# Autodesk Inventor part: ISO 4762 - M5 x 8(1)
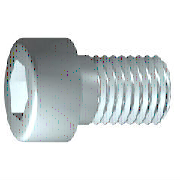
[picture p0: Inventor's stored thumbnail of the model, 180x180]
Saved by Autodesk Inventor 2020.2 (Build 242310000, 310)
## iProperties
Created: 2019-01
Part Number: ISO 4762 - M5 x 8(1)
Material: Edelstahl, 440C
Description: Innensechskantschraube
Document SubType Name: Modeling
Standard: ISO 4762
Designer: lutzd
Standard Revision: Fourth edition 2004-03-01
Standards Organization: ISO
Language: de-DE
Size Designation: M5 x 8
Categories: <MemberInstance><Categories><Category DisplayName="Verbindungselemente" InternalName="e4da775c-781d-43d5-af7c-5136215cf5a6" Mnemonic="FSTN"><Category DisplayNam
Mass: 3.06739 g
Surface Area: 3.99742 cm^2
Volume: 0.395792 cm^3
Density: 7.75 g/cm^3
Appearance: Semi-Polished(3)
IsCustomPart: 0
Author: lutzd
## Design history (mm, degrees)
body "Solid1"
sketch "Skizze1"
  geometry: L1 (-1.167, 0)-(8, 0); L2 (8, 0)-(8, 2.5); L3 (8, 2.5)-(2, 2.5); L4 (2, 2.5)-(1.509, 2.5); L5 (1.509, 2.5)-(0, 2.5); L6 (0, 2.5)-(0, 4.25); L7 (0, 4.25)-(-5, 4.25); L8 (-5, 4.25)-(-5, 2.309); L9 (-5, 2.309)-(-2.5, 2.309); L10 (-2.5, 2.309)-(-1.167, 0); L11 (-7.6, 0)-(10.6, 0) reference; L12 (0, -0.85)-(0, 5.1) reference; L13 (2, 2.5)-(0, 2.5)
  constraints: 22 end point, 6 parallel, 2 collinear, 2 perpendicular, 1 horizontal, 1 point on line
  dimensions: "d1" = 6 distance from line of L3.end L2 (= GEL); "d2" = 0.49086 distance of L4.end L3.end (computed from GAL); "d3" = 5 distance between parallel lines of L8 L6 (= KOH); "d4" = 2.5 distance of L8.end L9.end (= INTI); "d5" = 60 deg angle of L10 L1; "d6" = 5 diameter of L3 L1 (= GD); "d7" = 5 diameter of L5 L1 (= BDM); "d8" = 4.6188 diameter of L9 L1 (= 1.1547 x SW); "d9" = 8.5 diameter of L7 L1 (= KOD); "d26" = 8 distance between parallel lines of L12 L2 (= NLG)
workplane "Work Plane1"
fillet "Fillet2" dims "d30" = 0.1 (= R)
revolve "Körper" stored, may be unused: angle "d10" = 90 deg
sketch "Skizze2"
  geometry: L1 (0, -5.95)-(0, 5.95) reference; L2 (-5.95, 0)-(5.95, 0) reference; L3 (2.309, 0)-(1.155, -2); L4 (1.155, -2)-(-1.155, -2); L5 (-1.155, -2)-(-2.309, 0); L6 (-2.309, 0)-(-1.155, 2); L7 (-1.155, 2)-(1.155, 2); L8 (1.155, 2)-(2.309, 0); 2 further points
  constraints: 12 end point, 1 coincident, 1 horizontal alignment, 1 point on line, 12 other
extrude "Loch" join sketch "Skizze2" stored distance "d11" = 10; taper "d12" = 0 deg
fillet "Rundung1" dims "d17" = 0.5 (= RR)
feature "Gewinde" dims "d13" = 6 (= GEL), "d14" = 0
chamfer "Fase1" distance "d15" = 0.49076 (= -0.5 x SPD + 0.5 x GD); stored, may be unused: second distance "d16" = 0.49076 (= GUL), angle "d27" = 45 deg
other parameters: "GD" = 5 [user parameter; used in 2 equation terms], "NLG" = 8 [user parameter; used in 1 equation term], "GEL" = 6 [user parameter; used in 2 equation terms], "KOD" = 8.5 [user parameter; used in 1 equation term], "KOH" = 5 [user parameter; used in 1 equation term], "INTI" = 2.5 [user parameter; used in 1 equation term], "GAL" = 0.49076 (= 0.61345 x PTC) [user parameter; used in 1 equation term], "GUL" = 0.49076 (= 0.61345 x PTC) [user parameter; used in 1 equation term], "BDM" = 5 (= NND) [user parameter; used in 1 equation term], "SW" = 4 [user parameter; used in 2 equation terms], "RR" = 0.5 [user parameter; used in 1 equation term], "SPD" = 4.01848 (= NND - 1.2269 x PTC) [user parameter; used in 1 equation term], "d19" = 0, "d28" = 0, "d29" = 0, "R" = 0.1 [user parameter; used in 1 equation term], "TOA" = 30 deg [user parameter], "GD1" = 4.01848 (= THREADDIA - 1.2269 x PTC) [user parameter], "THREADDIA" = 5 [user parameter; used in 1 equation term], "FAWI" = 45 deg [user parameter], "TPU" = 12.5 (computed from PTC) [user parameter], "PTC" = 0.8 [user parameter; used in 5 equation terms], "NND" = 5 [user parameter; used in 2 equation terms], "E0" = 4.62 (= 1.155 x SW) [user parameter]
